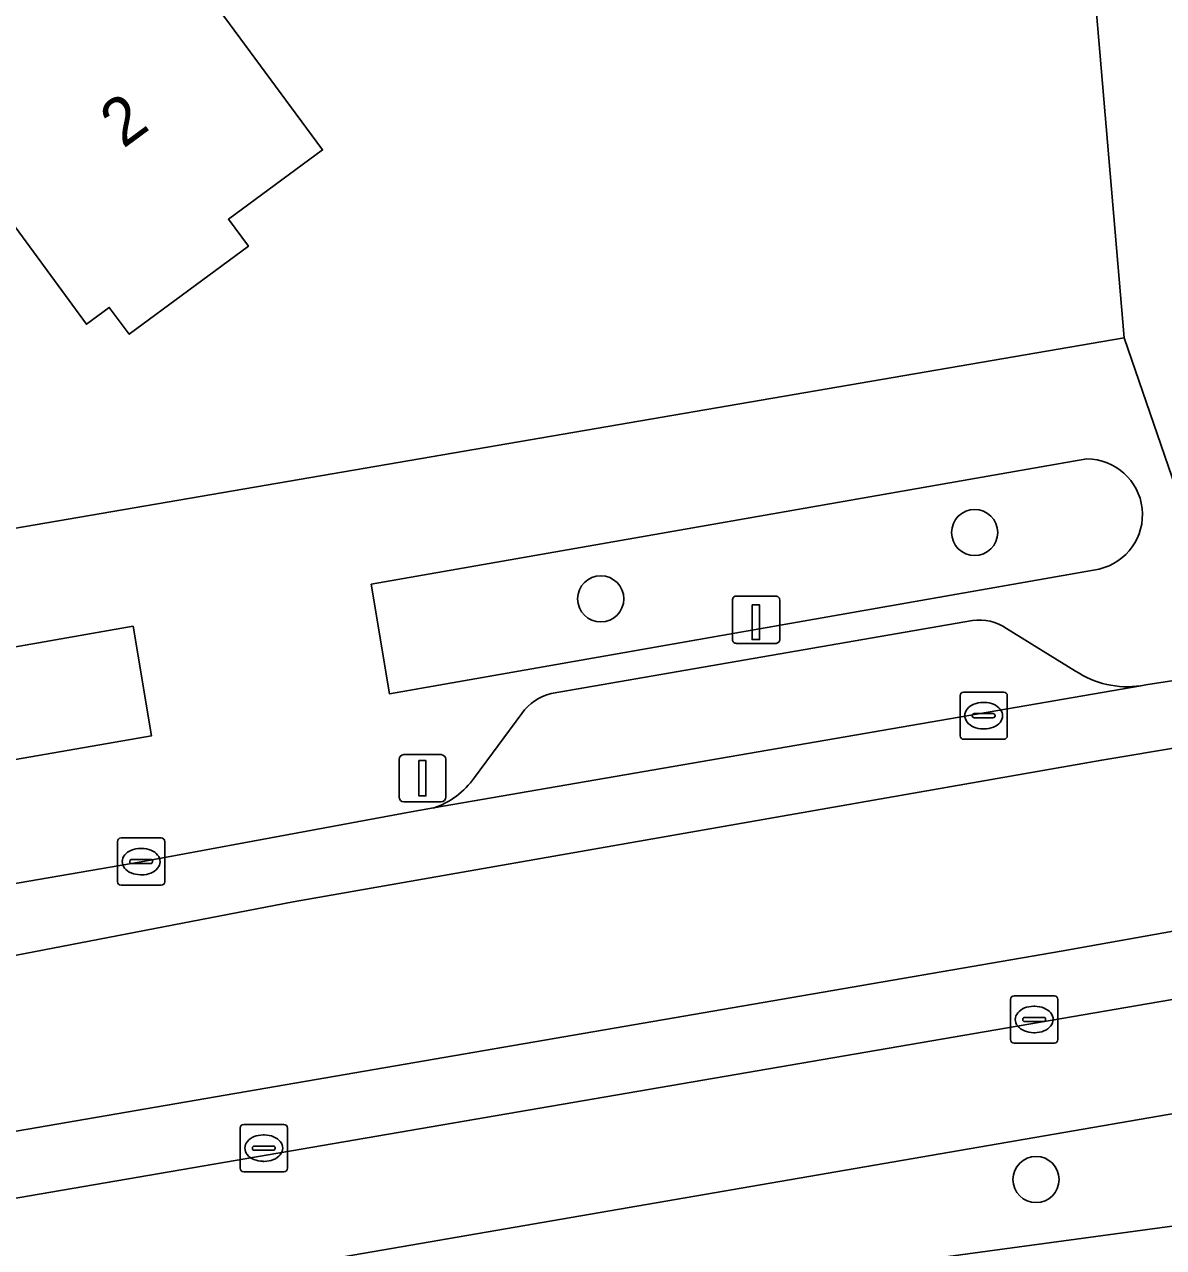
# Model space of a CAD drawing. Extents: x 163426 to 164192, y 380329 to 381641.
# Drawn here: x 163929.25 to 163953.37, y 381057.18 to 381083.09 of the extents above; entities that cross this region are included whole.
import ezdxf

# ---------------------------------------------------------------- set-up
doc = ezdxf.new("R2010")
doc.units = 0
for name, color, linetype in [('IMGEO_Boom', 7, 'Continuous'), ('IMGEO_Erf', 7, 'Continuous'), ('IMGEO_Groenvoorziening', 7, 'Continuous'), ('IMGEO_Kolk', 7, 'Continuous'), ('IMGEO_Laadpaal', 7, 'Continuous'), ('IMGEO_Lichtmast', 7, 'Continuous'), ('IMGEO_Pand', 7, 'Continuous'), ('IMGEO_Pand_nummerreeks', 7, 'Continuous'), ('IMGEO_Parkeervlak_open', 7, 'Continuous'), ('IMGEO_Rijbaan_lokaal_open', 7, 'Continuous'), ('IMGEO_Voetpad_open', 7, 'Continuous'), ('IMGEO_Waterloop', 7, 'Continuous')]:
    doc.layers.add(name, color=color, linetype=linetype)

msp = doc.modelspace()

# ---------------------------------------------------------------- linework, layer by layer
at = {"layer": 'IMGEO_Boom'}
for centre in [(163949.367, 381072.328), (163941.45, 381070.922), (163950.666, 381058.623)]:
    msp.add_circle(centre, 0.489, dxfattribs=at)
at = {"layer": 'IMGEO_Erf'}
for points in [[(163882.295, 381118.226), (163898.019, 381097.05), (163899.274, 381095.308), (163900.905, 381096.518), (163902.973, 381093.731), (163901.342, 381092.521), (163917.592, 381070.453), (163952.531, 381076.448), (163942.036, 381199.692)], [(163926.46, 381086.403), (163929.504, 381088.651), (163932.594, 381084.458), (163935.561, 381080.432), (163933.569, 381078.961), (163933.99, 381078.394), (163931.467, 381076.526), (163931.044, 381077.096), (163930.561, 381076.739), (163926.725, 381081.974)]]:
    msp.add_lwpolyline(points, dxfattribs=at)
at = {"layer": 'IMGEO_Groenvoorziening'}
for points in [[(163951.743, 381073.886), (163936.592, 381071.231), (163936.977, 381068.912), (163952.003, 381071.554)], [(163975.886, 381060.609), (163980.662, 381061.081), (163980.593, 381061.81), (163977.128, 381061.219), (163976.661, 381063.908), (163971.248, 381063.001), (163957.475, 381060.692), (163930.805, 381056.087)], [(163929.685, 381053.658), (163931.981, 381050.546), (163933.77, 381048.138), (163936.474, 381048.305), (163938.396, 381052.589), (163936.002, 381052.266), (163935.728, 381053.26), (163935.208, 381055.15), (163971.524, 381060.07), (163973.475, 381060.334), (163973.427, 381058.717), (163976.037, 381058.881), (163975.886, 381060.609)]]:
    msp.add_lwpolyline(points, dxfattribs=at)
msp.add_lwpolyline([(163926.009, 381066.988), (163931.936, 381068.019), (163931.548, 381070.342), (163925.609, 381069.297)], close=True, dxfattribs=at)
msp.add_arc((163951.739, 381072.705), 1.181, 282.8995, 89.824, dxfattribs=at)
at = {"layer": 'IMGEO_Kolk'}
for p, q in [((163949.057, 381068.022), (163949.057, 381068.874)), ((163949.132, 381068.948), (163949.984, 381068.948)), ((163949.545, 381068.728), (163949.57, 381068.728)), ((163950.058, 381068.874), (163950.058, 381068.022)), ((163949.316, 381068.442), (163949.316, 381068.454)), ((163949.359, 381068.491), (163949.757, 381068.491)), ((163949.8, 381068.454), (163949.8, 381068.442)), ((163949.754, 381068.405), (163949.356, 381068.405)), ((163949.984, 381067.948), (163949.132, 381067.948)), ((163949.568, 381068.168), (163949.543, 381068.168)), ((163931.294, 381065.858), (163932.146, 381065.858)), ((163931.219, 381064.932), (163931.219, 381065.784)), ((163931.707, 381065.638), (163931.732, 381065.638)), ((163932.22, 381065.784), (163932.22, 381064.932)), ((163931.478, 381065.352), (163931.478, 381065.364)), ((163931.521, 381065.401), (163931.919, 381065.401)), ((163931.962, 381065.364), (163931.962, 381065.352)), ((163931.916, 381065.315), (163931.518, 381065.315)), ((163931.73, 381065.078), (163931.705, 381065.078)), ((163932.146, 381064.858), (163931.294, 381064.858)), ((163950.202, 381062.514), (163951.054, 381062.514)), ((163950.127, 381061.588), (163950.127, 381062.44)), ((163950.615, 381062.294), (163950.64, 381062.294)), ((163951.128, 381062.44), (163951.128, 381061.588)), ((163950.386, 381062.008), (163950.386, 381062.02)), ((163950.824, 381061.971), (163950.426, 381061.971)), ((163950.429, 381062.057), (163950.827, 381062.057)), ((163950.87, 381062.02), (163950.87, 381062.008)), ((163950.638, 381061.734), (163950.613, 381061.734)), ((163951.054, 381061.514), (163950.202, 381061.514)), ((163933.816, 381058.863), (163933.816, 381059.715)), ((163933.891, 381059.789), (163934.743, 381059.789)), ((163934.817, 381059.715), (163934.817, 381058.863)), ((163934.304, 381059.569), (163934.329, 381059.569)), ((163934.075, 381059.283), (163934.075, 381059.295)), ((163934.513, 381059.246), (163934.115, 381059.246)), ((163934.118, 381059.332), (163934.516, 381059.332)), ((163934.559, 381059.295), (163934.559, 381059.283)), ((163934.327, 381059.009), (163934.302, 381059.009)), ((163934.743, 381058.789), (163933.891, 381058.789))]:
    msp.add_line(p, q, dxfattribs=at)
for points in [[(163949.057, 381068.022), (163949.057, 381068.874)], [(163949.132, 381068.948), (163949.984, 381068.948)], [(163950.058, 381068.874), (163950.058, 381068.022)], [(163949.984, 381067.948), (163949.132, 381067.948)], [(163931.294, 381065.858), (163932.146, 381065.858)], [(163931.219, 381064.932), (163931.219, 381065.784)], [(163932.22, 381065.784), (163932.22, 381064.932)], [(163932.146, 381064.858), (163931.294, 381064.858)], [(163950.202, 381062.514), (163951.054, 381062.514)], [(163950.127, 381061.588), (163950.127, 381062.44)], [(163951.128, 381062.44), (163951.128, 381061.588)], [(163951.054, 381061.514), (163950.202, 381061.514)], [(163933.816, 381058.863), (163933.816, 381059.715)], [(163933.891, 381059.789), (163934.743, 381059.789)], [(163934.817, 381059.715), (163934.817, 381058.863)], [(163934.743, 381058.789), (163933.891, 381058.789)]]:
    msp.add_lwpolyline(points, dxfattribs=at)
for centre, radius, start, end in [((163949.134, 381068.872), 0.0765, 91.552, 178.448), ((163949.134, 381068.872), 0.0765, 91.552, 178.448), ((163949.982, 381068.872), 0.0765, 1.552, 88.448), ((163949.982, 381068.872), 0.0765, 1.552, 88.448), ((163949.356, 381068.451), 0.0403, 85.8775, 175.7526), ((163949.353, 381068.441), 0.0366, 178.938, 274.7102), ((163949.757, 381068.448), 0.043, 264.8664, 352.4533), ((163949.761, 381068.453), 0.0386, 1.7309, 96.639), ((163949.134, 381068.024), 0.0765, 181.552, 268.448), ((163949.134, 381068.024), 0.0765, 181.552, 268.448), ((163949.982, 381068.024), 0.0765, 271.552, 358.448), ((163949.982, 381068.024), 0.0765, 271.552, 358.448), ((163931.296, 381065.782), 0.0765, 91.552, 178.448), ((163931.296, 381065.782), 0.0765, 91.552, 178.448), ((163932.144, 381065.782), 0.0765, 1.552, 88.448), ((163932.144, 381065.782), 0.0765, 1.552, 88.448), ((163931.518, 381065.361), 0.0403, 85.8775, 175.7526), ((163931.515, 381065.351), 0.0366, 178.938, 274.7102), ((163931.919, 381065.358), 0.043, 264.8664, 352.4533), ((163931.923, 381065.363), 0.0386, 1.7309, 96.639), ((163931.296, 381064.934), 0.0765, 181.552, 268.448), ((163931.296, 381064.934), 0.0765, 181.552, 268.448), ((163932.144, 381064.934), 0.0765, 271.552, 358.448), ((163932.144, 381064.934), 0.0765, 271.552, 358.448), ((163950.204, 381062.438), 0.0765, 91.552, 178.448), ((163950.204, 381062.438), 0.0765, 91.552, 178.448), ((163951.052, 381062.438), 0.0765, 1.552, 88.448), ((163951.052, 381062.438), 0.0765, 1.552, 88.448), ((163950.426, 381062.017), 0.0403, 85.8775, 175.7526), ((163950.423, 381062.007), 0.0366, 178.938, 274.7102), ((163950.827, 381062.014), 0.043, 264.8664, 352.4533), ((163950.831, 381062.019), 0.0386, 1.7309, 96.639), ((163950.204, 381061.59), 0.0765, 181.552, 268.448), ((163950.204, 381061.59), 0.0765, 181.552, 268.448), ((163951.052, 381061.59), 0.0765, 271.552, 358.448), ((163951.052, 381061.59), 0.0765, 271.552, 358.448), ((163933.893, 381059.713), 0.0765, 91.552, 178.448), ((163933.893, 381059.713), 0.0765, 91.552, 178.448), ((163934.741, 381059.713), 0.0765, 1.552, 88.448), ((163934.741, 381059.713), 0.0765, 1.552, 88.448), ((163934.115, 381059.292), 0.0403, 85.8775, 175.7526), ((163934.112, 381059.282), 0.0366, 178.938, 274.7102), ((163934.516, 381059.289), 0.043, 264.8664, 352.4533), ((163934.52, 381059.294), 0.0386, 1.7309, 96.639), ((163933.893, 381058.865), 0.0765, 181.552, 268.448), ((163933.893, 381058.865), 0.0765, 181.552, 268.448), ((163934.741, 381058.865), 0.0765, 271.552, 358.448), ((163934.741, 381058.865), 0.0765, 271.552, 358.448)]:
    msp.add_arc(centre, radius, start, end, dxfattribs=at)
for centre, major_axis, ratio, start_param, end_param in [((163949.544, 381068.448), (-0.387, 0.002), 0.722429, 4.712389, 7.853982), ((163949.569, 381068.448), (-0.39, 0.002), 0.717154, 1.570796, 4.712389), ((163931.706, 381065.358), (-0.387, 0.002), 0.722429, 4.712389, 7.853982), ((163931.731, 381065.358), (-0.39, 0.002), 0.717154, 1.570796, 4.712389), ((163950.614, 381062.014), (-0.387, 0.002), 0.722429, 4.712389, 7.853982), ((163950.639, 381062.014), (-0.39, 0.002), 0.717154, 1.570796, 4.712389), ((163934.303, 381059.289), (-0.387, 0.002), 0.722429, 4.712389, 7.853982), ((163934.328, 381059.289), (-0.39, 0.002), 0.717154, 1.570796, 4.712389)]:
    msp.add_ellipse(centre, major_axis=major_axis, ratio=ratio, start_param=start_param, end_param=end_param, dxfattribs=at)
at = {"layer": 'IMGEO_Laadpaal'}
for p, q in [((163944.24, 381070.896), (163944.24, 381070.055)), ((163944.24, 381070.896), (163944.24, 381070.055)), ((163945.156, 381070.98), (163944.315, 381070.98)), ((163945.156, 381070.98), (163944.315, 381070.98)), ((163945.24, 381070.064), (163945.24, 381070.905)), ((163945.24, 381070.064), (163945.24, 381070.905)), ((163944.324, 381069.98), (163945.165, 381069.98)), ((163944.324, 381069.98), (163945.165, 381069.98))]:
    msp.add_line(p, q, dxfattribs=at)
msp.add_lwpolyline([(163944.655, 381070.793), (163944.815, 381070.793), (163944.815, 381070.06), (163944.655, 381070.06), (163944.655, 381070.793)], dxfattribs=at)
for centre, start, end in [((163944.318, 381070.902), 92.4484, 184.2845), ((163944.318, 381070.902), 92.4484, 184.2845), ((163945.162, 381070.902), 2.4484, 94.2845), ((163945.162, 381070.902), 2.4484, 94.2845), ((163944.318, 381070.058), 182.4484, 274.2845), ((163944.318, 381070.058), 182.4484, 274.2845), ((163945.162, 381070.058), 272.4484, 4.2845), ((163945.162, 381070.058), 272.4484, 4.2845)]:
    msp.add_arc(centre, 0.0779, start, end, dxfattribs=at)
at = {"layer": 'IMGEO_Lichtmast'}
for p, q in [((163937.18, 381066.723), (163937.18, 381067.523)), ((163937.18, 381067.523), (163937.18, 381066.723)), ((163937.28, 381067.623), (163938.07, 381067.623)), ((163938.07, 381067.623), (163937.28, 381067.623)), ((163938.17, 381067.523), (163938.17, 381066.723)), ((163938.17, 381066.723), (163938.17, 381067.523)), ((163938.07, 381066.623), (163937.28, 381066.623)), ((163937.28, 381066.623), (163938.07, 381066.623))]:
    msp.add_line(p, q, dxfattribs=at)
msp.add_lwpolyline([(163937.6, 381067.498), (163937.75, 381067.498), (163937.75, 381066.748), (163937.6, 381066.748), (163937.6, 381067.498)], dxfattribs=at)
for centre, start, end in [((163937.28, 381067.523), 90, 180), ((163937.28, 381067.523), 90, 180), ((163938.07, 381067.523), 0, 90), ((163938.07, 381067.523), 360, 90), ((163937.28, 381066.723), 180, 270), ((163937.28, 381066.723), 180, 270), ((163938.07, 381066.723), 270, 0), ((163938.07, 381066.723), 270, 0)]:
    msp.add_arc(centre, 0.1, start, end, dxfattribs=at)
at = {"layer": 'IMGEO_Pand'}
msp.add_lwpolyline([(163932.594, 381084.458), (163929.504, 381088.651), (163926.46, 381086.403), (163924.738, 381088.734), (163922.88, 381087.362), (163921.708, 381088.948), (163920.231, 381090.947), (163917.51, 381088.914), (163918.462, 381087.627), (163918.977, 381086.931), (163924.111, 381080.059), (163926.725, 381081.974), (163930.561, 381076.739), (163931.044, 381077.096), (163931.467, 381076.526), (163933.99, 381078.394), (163933.569, 381078.961), (163935.561, 381080.432)], close=True, dxfattribs=at)
at = {"layer": 'IMGEO_Parkeervlak_open'}
for points in [[(163949.322, 381070.461), (163940.403, 381068.92)], [(163951.504, 381069.394), (163950.041, 381070.293)], [(163937.909, 381066.493), (163952.882, 381069.081)], [(163939.777, 381068.496), (163938.776, 381067.139)]]:
    msp.add_lwpolyline(points, dxfattribs=at)
for centre, radius, start, end in [((163949.483, 381069.53), 0.945, 53.8615, 99.8352), ((163952.601, 381071.035), 1.974, 236.2335, 278.1724), ((163940.684, 381067.831), 1.124, 104.4632, 143.7577), ((163937.354, 381068.142), 1.74, 288.5911, 324.7884)]:
    msp.add_arc(centre, radius, start, end, dxfattribs=at)
at = {"layer": 'IMGEO_Rijbaan_lokaal_open'}
for points in [[(163964.785, 381071.085), (163959.492, 381070.181), (163958.625, 381069.383), (163957.385, 381068.612), (163955.476, 381068.076), (163952.059, 381067.506), (163934.94, 381064.507), (163927.101, 381062.998), (163922.411, 381061.926), (163922.056, 381061.604), (163924.4, 381058.441), (163925.804, 381058.955), (163928.454, 381059.539), (163951.197, 381063.463), (163958.036, 381064.684)], [(163921.069, 381062.936), (163922.056, 381061.604), (163922.411, 381061.926), (163927.101, 381062.998), (163934.94, 381064.507), (163952.059, 381067.506), (163955.476, 381068.076), (163957.385, 381068.612), (163958.625, 381069.383), (163959.492, 381070.181), (163954.955, 381069.405), (163952.994, 381069.1), (163952.882, 381069.081), (163937.909, 381066.493), (163937.438, 381066.412), (163932.255, 381065.455), (163931.72, 381065.356), (163928.024, 381064.714), (163925.468, 381064.311)], [(163958.036, 381064.684), (163951.197, 381063.463), (163928.454, 381059.539), (163925.804, 381058.955), (163924.4, 381058.441), (163925.267, 381057.271), (163927.518, 381057.946), (163928.198, 381058.083), (163958.565, 381063.301)]]:
    msp.add_lwpolyline(points, dxfattribs=at)
at = {"layer": 'IMGEO_Voetpad_open'}
for points in [[(163942.458, 381205.65), (163941.323, 381205.509), (163940.722, 381205.435), (163941.853, 381200.072), (163942.036, 381199.692), (163952.531, 381076.448), (163954.955, 381069.405)], [(163952.882, 381069.081), (163952.994, 381069.1), (163954.955, 381069.405), (163952.531, 381076.448), (163917.592, 381070.453), (163901.342, 381092.521), (163899.274, 381095.308), (163898.019, 381097.05), (163882.295, 381118.226)], [(163952.003, 381071.554), (163936.977, 381068.912), (163936.592, 381071.231), (163951.743, 381073.886)], [(163940.403, 381068.92), (163949.322, 381070.461)], [(163950.041, 381070.293), (163951.504, 381069.394)], [(163938.776, 381067.139), (163939.777, 381068.496)], [(163985.768, 381068.033), (163983.394, 381067.628), (163978.296, 381066.796), (163973.765, 381065.996), (163962.395, 381063.969), (163958.565, 381063.301), (163928.198, 381058.083), (163928.393, 381057.003)], [(163925.342, 381065.391), (163927.85, 381065.847), (163928.024, 381064.714), (163931.72, 381065.356), (163932.255, 381065.455), (163937.438, 381066.412), (163937.909, 381066.493)], [(163925.556, 381056.187), (163930.805, 381056.087), (163957.475, 381060.692), (163971.248, 381063.001), (163976.661, 381063.908), (163980.336, 381064.524), (163983.854, 381065.112), (163985.881, 381065.478)]]:
    msp.add_lwpolyline(points, dxfattribs=at)
msp.add_lwpolyline([(163931.548, 381070.342), (163931.936, 381068.019), (163926.009, 381066.988), (163925.609, 381069.297)], close=True, dxfattribs=at)
for centre, radius, start, end in [((163951.739, 381072.705), 1.181, 282.8995, 89.824), ((163949.483, 381069.53), 0.945, 53.8615, 99.8352), ((163952.601, 381071.035), 1.974, 236.2335, 278.1724), ((163940.684, 381067.831), 1.124, 104.4632, 143.7577), ((163937.354, 381068.142), 1.74, 288.5911, 324.7884)]:
    msp.add_arc(centre, radius, start, end, dxfattribs=at)
at = {"layer": 'IMGEO_Waterloop'}
msp.add_lwpolyline([(163973.385, 381057.316), (163973.427, 381058.717), (163973.475, 381060.334), (163971.524, 381060.07), (163935.208, 381055.15), (163935.728, 381053.26), (163936.002, 381052.266), (163938.396, 381052.589)], close=True, dxfattribs=at)

# ---------------------------------------------------------------- texts
at = {"layer": 'IMGEO_Pand_nummerreeks'}
msp.add_text('2', height=1, rotation=36.4516, dxfattribs=at).set_placement((163931.341, 381080.448))

doc.saveas('drawing.dxf')
